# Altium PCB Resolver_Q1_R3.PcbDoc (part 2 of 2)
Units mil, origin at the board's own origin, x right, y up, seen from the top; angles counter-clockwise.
Board outline 2524 x 1600 mil, 2 copper layers (Top Layer, Bottom Layer), stack 62 mil thick; 100 components, 53 nets, 290 pads, 103 vias.
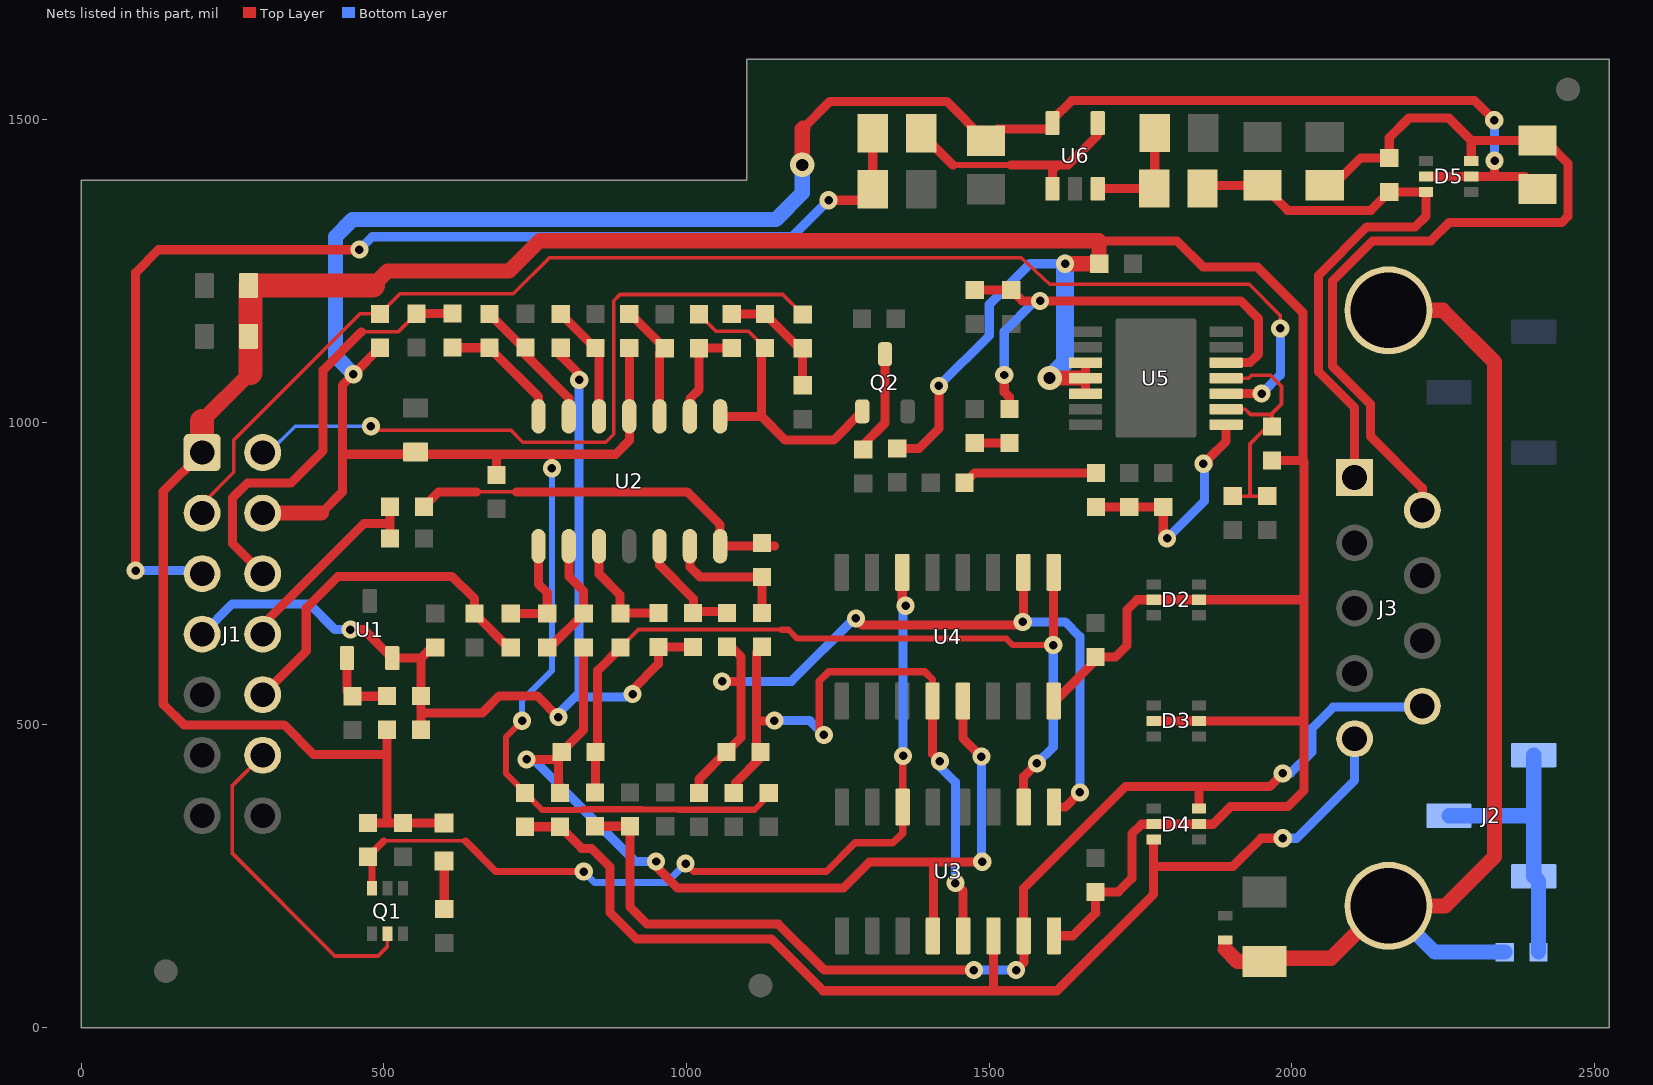
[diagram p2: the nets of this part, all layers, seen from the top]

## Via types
v1: diameter 30, hole 14, Top Layer to Bottom Layer, 80 vias
v2: diameter 23.5, hole 10, Top Layer to Bottom Layer, tented both sides, 12 vias
v3: diameter 40, hole 20, Top Layer to Bottom Layer, 4 vias
v4: diameter 30, hole 14, Top Layer to Bottom Layer, tented both sides, 3 vias
v5: diameter 23.5, hole 10, Top Layer to Bottom Layer, 3 vias
v6: diameter 30, hole 14, Top Layer to Bottom Layer, tented top, 1 vias

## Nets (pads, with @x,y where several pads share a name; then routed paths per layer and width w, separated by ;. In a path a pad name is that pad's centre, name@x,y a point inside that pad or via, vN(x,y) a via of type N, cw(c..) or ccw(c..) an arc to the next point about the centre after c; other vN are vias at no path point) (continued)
ICOS+: R19.1 R21.1 R22.2 U3.1 U4.2 | length 1370.7
  Top Layer w6: v1@1274.95,665 1271.94,668.02 v1(1280,676.08)
  Top Layer w15: R22.2@1020.74,387.81 1020.74,410.15 1066.14,455.54 R19.1@1066.36,455.54 1090.44,479.62 1090.44,571 ; v1(1059,571.97) 1089.47,571.97 1090.44,571 ; R21.1@1071.46,631.44 1090.44,612.47 1090.44,571 ; v1(1280,676.08) v1@1290,666.08 ; v1@1290,665 v4@1555.57,665 ; v4@1551.28,666 v4(1555.57,670.28) 1556.57,671.29 U4.2@1556.57,752.14 ; U3.1@1607.14,364.35 1625.68,364.35 v1(1650,388.67)
  Bottom Layer w15: v1@1063.21,571.97 1173.5,571.97 1277.61,676.08 v1(1280,676.08) ; v4(1555.57,670.28) 1625.64,670.28 1650,645.92 v1(1650,388.67)
ICOS-: R17.1 R18.2 R19.2 U3.13 U4.12 | length 1122.3
  Top Layer w12: v1(1227.2,483.67) 1219.44,491.42 1219.44,572.48 1234.98,588.02 1393.54,588.02 1406.57,574.99 U4.12@1406.57,539.54
  Top Layer w15: R18.2@1078.23,387.81 1078.23,387.86 1081.18,390.81 1081.18,404.44 1122.36,445.63 R19.2@1122.36,455.54 1116.02,461.89 1116.02,506.83 ; R17.1@1125,629.15 1116.02,620.17 1116.02,506.83 ; v1(1145.22,507.21) 1144.84,506.83 1116.02,506.83 ; U4.12@1406.57,539.54 1406.57,452.2 v1(1418.78,440) ; v1(1444.37,238.88) 1457.14,226.11 U3.13@1457.14,151.75
  Bottom Layer w15: v1(1145.22,507.21) 1203.65,507.21 v1(1227.2,483.67) ; v1(1418.78,440) 1418.78,431.22 1444.37,405.63 v1(1444.37,238.88)
INH: J1.12 Q1.2 | length 537.1
  Top Layer w6: J1.12@300,450 250,400 250,287.54 419.26,118.28 490.41,118.28 506.04,133.91 Q1.2@506.04,155.22
INH_CMOS: Q1.6 R26.1 U3.6 U4.6 | length 1457.4
  Top Layer w6: 499.82,308.5 634.54,308.5
  Top Layer w12: Q1.6@480.45,230.02 480.45,275.56 R26.1@473.82,282.19 499.82,308.19 499.82,308.5 ; 634.54,308.5 685.19,257.86 v1(830.31,257.86) ; v1(998.71,271.02) 1011.68,258.05 1231.31,258.05 1278.59,305.32 1341.4,305.32 1357.14,321.07 U3.6@1357.14,364.35 1357.14,448.24 v1(1357.9,449)
  Top Layer w15: U4.6@1356.57,752.14 1356.57,702.43 v4(1362,697)
  Bottom Layer w12: v1(830.31,257.86) 848.27,239.9 967.59,239.9 v1(998.71,271.02)
  Bottom Layer w15: v1(1357.9,449) 1357.9,692.9 v4(1362,697)
ISIN+: R7.1 R10.1 R11.2 U3.2 U4.1 | length 1414.2
  Top Layer w6: R10.1@891.26,627.97 920.94,657.65 1168.25,657.65 1168.62,657.28
  Top Layer w10: 1157,657.28 1168.62,657.28 1183.39,642.51 1212.23,642.51 1212.36,642.65 1528.31,642.65 1538.95,632 v6(1606,632)
  Top Layer w15: R11.2@849.01,388.67 850,389.65 R7.1@850,455.54 853.19,458.73 853.19,589.9 R10.1@891.26,627.97 ; U3.2@1557.14,364.35 1557.14,414.59 v1(1579,436.44) ; v6@1606.57,632 U4.1@1606.57,752.14
  Bottom Layer w15: v1(1579,436.44) 1606,463.45 v6(1606,632)
ISIN-: R5.1 R6.2 R7.2 U3.12 U4.13 | length 1579.8
  Top Layer w15: v1(735.96,443.05) 781.5,443.05 R7.2@788.46,450 ; R6.2@791.26,387.81 788.46,390.61 R7.2@788.46,450 ; R5.1@830.31,627.97 830.31,491.86 R7.2@794,455.54 R7.2@788.46,450 ; v1(950,274.46) 950,266.22 985.84,230.38 1259.35,230.38 1302.31,273.33 1481.98,273.33 v4@1488.75,280.09 ; U3.12@1407.14,151.75 1407.14,169.91 1408,170.76 1408,271.87 ; U4.13@1456.57,539.54 1456.57,478.37 v1(1487.19,447.76)
  Bottom Layer w15: v1(735.96,443.05) 746.89,443.05 915.47,274.46 v1(950,274.46) ; v1(1487.19,447.76) 1487.19,275.49 v4(1488.75,273.94)
NetC9_1: C9.1 R27.2 R28.1 U5.1 | length 394.2
  Top Layer w15: R27.2@1676.45,860.05 R28.1@1731.45,860.05 C9.1@1787.65,860.05 1787.65,814.37 v1(1793.91,808.1) ; v1@1861.93,931.39 1861.93,939.39 1891.46,968.92 U5.1@1891.46,996.12
  Bottom Layer w15: v1(1793.91,808.1) 1856,870.19 1856,925.46 v1@1861.93,931.39
  other v1: 1854,931.46
NetC10_2: C10.2 R27.1 | length 223.5
  Top Layer w15: C10.2@1459.57,900 1475.63,916.05 R27.1@1676.45,916.05
NetC11_1: C11.1 R35.1 U2.2 | length 173.1
  Top Layer w15: U2.2@1005.68,1009.86 1005.68,1038.84 1020.74,1053.91 C11.1@1020.74,1122.36 1074.71,1122.36 R35.1@1075,1122.65
NetC11_2: C11.2 Q2.1 R31.1 U2.1 | length 518.5
  Top Layer w6: C11.2@1020.74,1178.36 1048.45,1150.65 1102,1150.65 R31.1@1130,1122.65
  Top Layer w15: U2.1@1055.68,1009.86 1123.99,1009.86 ; R31.1@1130,1122.65 1123.99,1116.64 1123.99,1009.86 ; Q2.1@1290.6,1018.08 1243.11,970.59 1163.25,970.59 1123.99,1009.86
NetC12_2: C12.2 R33.1 R36.2 U5.2 U5.4 | length 447.3
  Top Layer w6: U5.2@1891.46,1021.71 1923.11,1021.71 1931.91,1012.9 1965.78,1012.9 1982.99,1030.11 1982.99,1059.43 1964.86,1077.56 1933.53,1077.56 1928.86,1072.89 U5.4@1891.46,1072.89 U5.4@1892.17,1072.17 ; C12.2@1902.5,878 1930.93,878 ; R36.2@1959.36,878 1930.93,878 ; 1967.3,1011.38 1967.3,986.28 1953.05,986.28 1930.93,964.16 1930.93,878
NetC13_2: C13.2 R31.2 R34.1 R35.2 | length 201.6
  Top Layer w15: R35.2@1075,1178.65 R31.2@1130,1178.65 1186.41,1122.24 R34.1@1192.03,1122.24 C13.2@1192.03,1061.04
NetC14_2: C14.2 R39.1 | length 57.4
  Top Layer w15: C14.2@1476.23,965.72 R39.1@1533.62,965.72
NetC15_1: C15.1 R39.2 R40.1 U5.5 | length 822
  Top Layer w15: R40.1@1476.23,1218.5 C15.1@1536.47,1218.5 1554.41,1200.57 1588.16,1200.57 1915.37,1200.57 1945,1170.93 1945,1112.68 1930.8,1098.48 U5.5@1891.46,1098.48 ; v1(1525,1078.11) 1525,1050.34 1533.62,1041.72 R39.2@1533.62,1021.72
  Bottom Layer w15: v1(1525,1078.11) 1525,1149.8 1575.77,1200.57 v1@1588.16,1200.57
  other v1: 1584.16,1200.57
NetD1_1: D1.1 R14.2 | length 79.5
  Top Layer w15: D1.1@599.26,275.2 600,274.46 R14.2@600,196
NetJ2_1: J2.1 J2.2 J2.3 R52.1 | length 469.5
  Bottom Layer w25: J2.2@2259.73,350 2397.47,350 2399.69,352.21 ; J2.1@2399.69,450 2399.69,352.21 ; R52.1@2407.71,124.67 2407.71,241.98 J2.3@2399.69,250 2399.69,352.21
NetQ2_3: Q2.3 R32.1 | length 172.4
  Top Layer w15: R32.1@1292.22,955.01 1292.22,963.07 1328,998.85 Q2.3@1328,1112.57
NetR3_1: R3.1 R8.2 U1.1 | length 124
  Top Layer w15: U1.1@439.39,610.41 439.39,556.57 R8.2@448.54,547.42 504.89,547.42 R3.1@505.5,548.04
NetR4_1: R4.1 R5.2 U2.9 | length 205
  Top Layer w15: R4.1@770.04,627.97 774.31,627.97 R5.2@830.31,683.97 830.31,720.83 805.68,745.46 U2.9@805.68,795.29
NetR4_2: R4.2 R9.1 U2.8 | length 177.5
  Top Layer w15: R9.1@709.81,683.97 R4.2@770.04,683.97 770.04,718.19 755.68,732.55 U2.8@755.68,795.29
NetR10_2: R10.2 R12.2 U2.10 | length 188.9
  Top Layer w15: U2.10@855.68,795.29 855.68,749.32 890,715 890,685.23 R10.2@891.26,683.97 892.33,685.04 R12.2@953.62,685.04
NetR16_1: R16.1 R17.2 U2.13 | length 217.3
  Top Layer w15: U2.13@1005.68,795.29 1005.68,761.25 1022.39,744.54 R16.1@1125,744.54 1125,693.16 R17.2@1129.01,689.16
NetR16_2: R16.2 R20.1 U2.14 | length 646.9
  Top Layer w6: 653.17,885.06 719.59,885.06
  Top Layer w15: R20.1@566.3,860.57 590.79,885.06 653.17,885.06 ; 719.59,885.06 1001.13,885.06 1055.68,830.51 U2.14@1055.68,795.29 1145.22,795.29
NetR21_2: R21.2 R23.2 U2.12 | length 192.2
  Top Layer w15: U2.12@955.68,795.29 955.68,764.25 1012,707.93 1012,686.32 1013.13,687.44 R21.2@1071.46,687.44
NetR29_1: R29.1 R37.2 U2.3 | length 197.9
  Top Layer w15: R29.1@905.68,1178.65 907.91,1178.65 R37.2@964.2,1122.36 955.68,1113.84 U2.3@955.68,1009.86
NetR41_1: R41.1 R42.2 U2.6 | length 226
  Top Layer w15: R41.1@674.47,1179.11 730.18,1123.4 R42.2@734.21,1123.4 734.21,1111.45 805.68,1039.99 U2.6@805.68,1009.86
NetR41_2: R41.2 R43.1 U2.7 | length 208
  Top Layer w15: R43.1@613.65,1123.69 614.23,1123.11 R41.2@674.47,1123.11 755.68,1041.9 U2.7@755.68,1009.86
NetR44_2: R44.2 R45.2 U2.5 | length 196.2
  Top Layer w15: R45.2@792.42,1179.11 848.58,1122.94 R44.2@849.84,1122.94 855.68,1117.11 U2.5@855.68,1009.86
NetR49_1: R49.1 U6.1 U6.4 | length 396.4
  Top Layer w10: 1440.26,1425 1536.32,1425
  Top Layer w15: R49.1@1387.8,1477.46 1440.26,1425 ; 1536.32,1425 1613.37,1425 ; U6.1@1604.57,1385.87 1604.57,1416.2 1613.37,1425 ; U6.4@1679.37,1494.13 1679.37,1474.13 1630.24,1425 1613.37,1425
NetR50_2: R50.2 R51.2 U6.3 | length 189.5
  Top Layer w15: U6.3@1679.37,1385.87 1762.05,1385.87 R50.2@1772.64,1396.46 ; R50.2@1772.64,1386.46 R50.2@1772.64,1396.46 ; R51.2@1773.57,1477.92 1773.57,1406.23 1772.64,1405.3 R50.2@1772.64,1396.46
NTC: C22.1 J1.5 R49.2 | length 1971.7
  Top Layer w15: v1(90,755) 90,1247.33 127.67,1285 459.57,1285 v1(459.75,1285.18) ; v1(1234.72,1366.74) 1289.55,1366.74 C22.1@1307.8,1385 R49.2@1307.8,1477.46
  Bottom Layer w15: v1(90,755) 195,755 J1.5@200,750 ; v1(459.75,1285.18) 480.99,1306.41 1174.39,1306.41 v1(1234.72,1366.74)
NTC+: C21.2 C23.1 D5.6 J3.6 R48.1 | length 1501.8
  Top Layer w15: C23.1@2054.45,1391.34 2068.13,1391.34 2113.25,1436.46 C21.2@2161,1436.46 2161,1470.04 2193.64,1502.68 2259.26,1502.68 2296.45,1465.48 ; J3.6@2215.61,854.76 2215.61,891.34 2130,976.95 2130,1030 2067.06,1092.94 2067.06,1233.25 2133.6,1299.79 2229.67,1299.79 2259.7,1329.82 2445.97,1329.82 2456.15,1340 2456.15,1427.72 2418.46,1465.41 R48.1@2405.58,1465.41 2395.58,1455.41 2385.37,1465.62 2296.59,1465.62 2296.45,1465.48 ; D5.6@2296.45,1431.64 2296.45,1465.48
NTC-: C21.1 C24.1 D5.3 J3.1 R50.1 | length 1017.5
  Top Layer w15: R50.1@1852.64,1396.46 1857.76,1391.34 C24.1@1951.81,1391.34 1993.15,1350 2130.55,1350 C21.1@2161,1380.46 D5.3@2221.65,1380.46 2221.65,1340.58 2203.73,1322.66 2124.12,1322.66 2044.18,1242.72 2044.18,1083.47 2103.8,1023.85 J3.1@2103.8,908.69
OCOS: C8.2 J1.8 R20.2 | length 347.7
  Top Layer w15: J1.8@300,650 300,665.63 467.51,833.14 510.25,833.14 ; C8.2@510.25,808.1 510.25,833.14 ; R20.2@510.25,860.57 510.25,833.14
OEXC: C16.2 J1.6 R43.2 | length 713.6
  Top Layer w6: 463.02,1149.26 523.69,1149.26 C16.2@553.84,1179.4
  Top Layer w15: J1.6@300,750 250,800 250,874.94 275.06,900 346.95,900 400,953.05 400,1086.23 463.02,1149.26 ; C16.2@553.84,1179.4 554.13,1179.69 R43.2@613.65,1179.69
OSIN: C3.2 J1.10 R9.2 | length 595.1
  Top Layer w15: J1.10@300,550 372.05,622.04 372.05,692.88 424.63,745.46 612.68,745.46 650,708.14 C3.2@650,683.97 706,627.97 R9.2@709.81,627.97
OT/SHDN: J1.3 R46.1 U5.3 | length 2235.1
  Top Layer w6: J1.3@200,850 200,864.95 252.3,917.25 252.3,970.73 460.68,1179.11 R46.1@493.74,1179.11 526.79,1212.15 713.95,1212.15 773.72,1271.93 1552.95,1271.93 1600,1227.87 1929.54,1227.87 1981,1176.41 v1(1981,1155)
  Top Layer w15: U5.3@1891.46,1047.3 v1(1950,1047.3)
  Bottom Layer w15: v1(1950,1047.3) 1981,1078.3 v1(1981,1155)
PWM: J1.2 R34.2 | length 1164.9
  Top Layer w6: v1(478.82,993.5) 485.63,986.69 710.12,986.69 729.77,967.04 866.79,967.04 879.81,980.05 879.81,1200.57 890.41,1211.17 1159.1,1211.17 R34.2@1192.03,1178.24
  Bottom Layer w6: J1.2@300,950 310.19,950 353.69,993.5 v1(478.82,993.5)
SHIELD_GND: C19.1 J3.10 J3.11 R47.2 R52.2 | length 1798.1
  Top Layer w15: 1890,129.77 R47.2@1890,144.8
  Top Layer w25: 1890,129.77 1910.22,109.54 C19.1@1955,109.54 ; C19.1@1955,114.54 2064.78,114.54 2151.05,200.82 2253.41,200.82 2335,282.41 2335,1099.55 2249.48,1185.07 J3.10@2151.05,1185.07
  Bottom Layer w25: J3.11@2159.7,201.01 2236.05,124.67 R52.2@2351.71,124.67
SIN+: D4.6 J3.9 R11.1 R13.2 U3.15 | length 1846.4
  Top Layer w15: R11.1@849.01,332.67 R13.2@906.57,332.67 906.57,225.79 906.9,205 906.9,199.18 934.95,171.13 1151.92,171.13 1228.05,95 v1(1475,95) ; v1(1544.49,95) 1557.62,108.13 1557.62,139.52 1557.14,140 U3.15@1557.14,151.75 1557.14,230.16 1725.22,398.24 1844.91,398.24 ; D4.6@1846.67,361.61 1846.67,396.48 1844.91,398.24 ; v1(1985,420) 1963.24,398.24 1844.91,398.24
  Bottom Layer w15: v1(1475,95) v1(1544.49,95) ; v1(1985,420) 1997.79,420 2032.94,455.15 2032.94,493.97 2068.33,529.36 J3.9@2206.96,529.36
SIN-: D4.3 J3.5 R2.1 R6.1 U3.14 | length 1898.2
  Top Layer w15: R2.1@733.43,331.81 R6.1@791.26,331.81 826.92,296.15 843.09,296.15 874,265.24 874,190.03 917.4,146.63 1140.24,146.63 1225.87,61 1612.19,61 1771.87,220.68 1771.87,266.5 ; 1507.14,65 U3.14@1507.14,151.75 ; D4.3@1771.87,310.43 1771.87,266.5 ; v1(1985,312.93) 1949.3,312.93 1902.53,266.16 1772.21,266.16 1771.87,266.5
  Bottom Layer w15: v1(1985,312.93) 2008.07,312.93 2103.8,408.65 2103.8,466.18 J3.5@2095.14,474.83
Va: C1.1 C2.1 C5.2 C6.2 C7.2 D1.2 D2.2 D2.5 D3.2 D3.5 D4.2 D4.5 J1.1 R1.2 R25.2 R26.2 R30.2 R33.2 U3.16 U4.16 U5.10 U5.11 U5.12 | length 6331.2
  Top Layer w15: J1.1@195,955 J1.1@200,950 135.83,885.82 135.83,534.17 170,500 335.52,500 384.64,450.88 505.45,450.88 ; R26.2@473.82,338.19 505.45,338.19 ; R1.2@505.5,492.04 505.45,450.88 ; D1.2@599.26,338.19 R25.2@531.63,338.19 505.45,338.19 ; R30.2@1348.22,956.93 1384.42,956.93 1417.11,989.63 v1(1417.11,1060.08) ; U4.16@1606.57,539.54 1608.91,539.54 C7.2@1681.83,612.47 ; U3.16@1607.14,151.75 1638.22,151.75 1676.25,189.77 1675.88,190.13 C6.2@1675.88,224.28 1713.46,224.28 1735.86,246.68 1735.86,320.04 1751.84,336.02 D4.2@1771.87,336.02 D4.5@1846.67,336.02 1869.8,336.02 1898.79,365 1993.35,365 2020,391.65 2020,505 ; U5.11@1658.76,1073.3 U5.11@1659.17,1072.89 ; U5.12@1659.17,1047.3 U5.11@1659.17,1072.89 ; U5.10@1659.17,1098.48 U5.11@1659.17,1072.89 ; C7.2@1675.88,612.47 C7.2@1681.83,612.47 ; 1681.76,1299.79 1810.17,1299.79 1853.48,1256.48 1942.98,1256.48 2018.17,1181.3 2018.17,936.95 ; D3.2@1771.87,506.83 D3.5@1846.67,506.83 2018.17,506.83 2020,505 ; R33.2@1967.3,930.28 1973.98,936.95 2018.17,936.95 ; 505.45,338.19 505.45,450.88 ; C7.2@1681.83,612.47 1709,612.47 1727.86,631.33 1727.86,690.11 1744.58,706.83 D2.2@1772.04,706.83 D2.5@1846.85,706.83 2018.17,706.83 2020,705 ; 2018.17,936.95 2020,935.12 2020,705 ; 2020,505 2020,705
  Top Layer w25: 200,1001.9 280,1081.9 ; 481.81,1225.78 506.04,1250 707.27,1250 757.05,1299.79 1681.76,1299.79 C5.2@1681.81,1261.91 v1(1625.49,1261.91) ; v3(1600,1073.3) U5.11@1658.76,1073.3
  Top Layer w40: J1.1@200,950 200,1001.9 ; 280,1081.9 280,1225.78 481.81,1225.78
  Bottom Layer w15: v1(1417.11,1060.08) 1500.23,1143.2 1500.23,1194.6 1567.55,1261.91 v1@1625.45,1261.91
  Bottom Layer w30: v3(1600,1073.3) 1625.45,1098.75 v1@1625.45,1261.91
Vcc: C4.1 C18.2 C20.1 D5.2 D5.5 J1.4 R2.2 R15.2 R29.2 R46.2 R48.2 U2.4 U6.5 | length 4777.1
  Top Layer w10: v1(728.51,506.83) 702.17,480.49 702.17,419.62 729.05,392.73 728.51,392.73 R2.2@733.43,387.81 761.43,359.81 827.95,359.81 828.93,360.79 926.91,360.79 927.16,360.54 985.26,360.54 985.87,359.93 1112.28,359.93 1112.41,359.81 1136.03,383.43 R15.2@1136.03,387.81 ; 777.39,947.14 777.39,924.39 v1(777.74,924.04)
  Top Layer w15: 396.84,850 431.67,884.82 431.67,947.14 ; R46.2@493.74,1123.11 v1(450,1079.37) 431.67,1061.04 431.67,947.14 ; C18.2@686.19,913.06 686.19,947.14 ; R29.2@905.68,1122.65 U2.4@905.68,1009.86 905.68,969.87 882.95,947.14 777.39,947.14 686.19,947.14 ; 1192.81,1485.69 1237.12,1530 1429.74,1530 C20.1@1494.74,1465 1513.88,1484.13 1604.57,1484.13 U6.5@1604.57,1494.13 1604.57,1499.59 1636.36,1531.38 2302.09,1531.38 v1(2334.48,1499) ; D5.2@2221.65,1406.05 D5.5@2296.45,1406.05 2335,1406.05 ; v1(2335,1432.05) 2335,1406.05 ; R48.2@2386.45,1385.46 2386.45,1404.54 2384.94,1406.05 2335,1406.05 ; 431.67,947.14 552.64,947.14 686.19,947.14
  Top Layer w25: J1.4@300,850 396.84,850 ; v3(1191.41,1425.31) 1191.41,1484.29 1192.81,1485.69
  Bottom Layer w10: v1(728.51,506.83) 728.51,540.67 777.74,589.9 v1(777.74,924.04)
  Bottom Layer w15: v1(2334.48,1499) 2335,1498.48 v1(2335,1432.05)
  Bottom Layer w25: v1(450,1079.37) 420.03,1109.34 420.03,1306.41 448.62,1335 1147.84,1335 1191.41,1378.57 v3(1191.41,1425.31)
VREF1/2: C17.1 J1.7 R1.1 R3.2 R12.1 R23.1 R45.1 U1.2 | length 1708.1
  Top Layer w15: v1(445,657.65) 466.95,657.65 U1.2@514.19,610.41 561.55,610.41 ; R1.1@561.38,491.97 R1.1@561.38,492.04 ; R3.2@561.38,548.04 R3.2@561.38,548.23 ; R1.1@561.5,492.04 561.5,519.97 ; R3.2@561.5,548.04 561.5,519.97 ; R3.2@561.55,548.04 561.55,610.41 ; C17.1@585,627.97 579.12,627.97 561.55,610.41 ; v1(788.46,513.04) 753.53,547.97 691.11,547.97 663.11,519.97 561.5,519.97 ; R45.1@792.42,1123.11 792.42,1109.67 822.88,1079.2 v1(822.88,1070.11) ; v1(911,551) 911,558.51 953.62,601.13 R12.1@953.62,629.04 R23.1@1010.73,629.04
  Bottom Layer w15: J1.7@200,650 200.1,650 250,699.9 377.04,699.9 419.29,657.65 v1(445,657.65) ; v1(788.46,513.04) 788.46,518.77 816.21,546.52 ; v1(822.88,1070.11) 822.88,553.2 816.21,546.52 ; v1(911,551) 903.49,551 899.01,546.52 816.21,546.52
pads on no net: FID1.1 FID2.1 FID3.1 J3.2 J4.1 J4.2 J4.3 U3.4 U4.4 U5.7 U5.8

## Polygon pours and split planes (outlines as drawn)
GND on Bottom Layer "BOTTOM_LAYER_GND_P000" (solid, remove dead copper, pour order 0): 2400,50 2470,120 2470,1485.32 2405.32,1550 1200,1550 1150,1500 1150,1350 100,1350 50,1300 50,100 100,50
Vcc on Top Layer "TOP_LAYER_VCC_P006" (solid, remove dead copper, pour order 6): 50,706.83 50,330.04 99.75,280.28 1105.28,280.28 1194,369 1194,1281.3 624.47,1281.3
Vcc on Top Layer "TOP_LAYER_VCC_P004" (solid, remove dead copper, pour order 4): 1399.89,1375 2350.28,1375 2382.99,1407.71 2382.99,1505.54 2338.53,1550 1200,1550 1150,1500 1150,1375
Va on Top Layer "TOP_LAYER_VA_P002" (solid, remove dead copper, pour order 2): 177.12,913.62 453.5,1190 2009.47,1190 2018.17,1181.3 2018.17,1259.68 1942.85,1335 523.18,1335 453.95,1265.78 291.46,1265.78 177.12,1151.44

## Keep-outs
Keep-Out Layer:
  text ".Layer_Name" at 577,-858.49 h60

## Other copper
Top Layer:
  rectangle net Va: 1600,1053.91 1682.3,1093.66
  text ".Layer_Name" at 577,-858.49 h60
Bottom Layer:
  text ".Layer_Name" at 577,-858.49 h60

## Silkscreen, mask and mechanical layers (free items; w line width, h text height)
Top Overlay:
  text "DAC" at 366.95,920 h40 r90
  text "EXC" at 366.95,720 h40 r90
  text "NTC" at 160.53,715 h40 r90
  text "X-  X+" at 1961.45,629.15 h60 r90
  text "COS" at 366.95,606.9 h40 r90
  text "SIN" at 366.95,516.97 h40 r90
  text "C-  C+" at 1959.36,460.12 h60 r90
  text "INH" at 366.95,419.41 h40 r90
  text "CTL" at 369.65,312.93 h40 r90
  text "S-  S+" at 1961.12,293.12 h60 r90
  text "RESOLVER" at 724.61,124.09 h80
  text "'.PRJ_Number'.PCB_Rev" at 726.2,50 h70
  text ".Layer_Name" at 577,-858.49 h60
Bottom Overlay:
  text ".Layer_Name" at 577,-858.49 h60
Top Paste:
  text ".Layer_Name" at 577,-858.49 h60
Bottom Paste:
  text ".Layer_Name" at 577,-858.49 h60
Top Solder:
  rectangle: 1705,979 1845,1167.36
  text ".Layer_Name" at 577,-858.49 h60
  text ".Layer_Name" at 577,-858.49 h60
Bottom Solder:
  text ".Layer_Name" at 577,-858.49 h60
Drill Guide:
  text ".Layer_Name" at 577,-858.49 h60
M1 Board Outline:
  the board outline again, w10
  text ".Layer_Name" at 577,-858.49 h60
M2 Board Dimensions:
  rectangle: 0,-275 125,-150
  rectangle: 125,-400 500,-275
  lines w7: 0,-275 1000,-275 ; 125,-400 125,-150 ; 250,-400 250,-150 ; 500,-400 500,-150 ; 750,-400 750,-150 ; 0,-400 1000,-400 1000,-150 0,-150 0,-400
  text ".Layer_Name" at 577,-858.49 h60
M3 3D STEP Top:
  text ".Layer_Name" at 577,-858.49 h60
M4 3D STEP Bottom:
  text ".Layer_Name" at 577,-858.49 h60
M5 Assembly Top:
  lines w10: -292,-930.17 6308,-930.17 ; -292,-726.83 6310,-726.83 ; -292,-523.5 -292,-1133.5 3713,-1133.5 6310,-1133.5 6310,-523.5 -291.5,-523.5 -291.5,-1133.5 1284,-1133.5 ; 2173,-1133.5 2173,-523.5 ; 3440,-726.83 3440,-523.5 ; 4280,-726.83 4280,-523.5 ; 4902,-1140 4902,-937.17
  text "COMPONENTS MARKED 'DNP' SHOULD NOT BE POPULATED." at 1153.5,-318.5 h60
  text "ASSEMBLY VARIANT:" at 1153,-434 h60
  text ".VariantName" at 2189,-434 h60
  text "PCB VIEWED FROM TOP SIDE" at -228.5,-655.67 h60
  text "BOARD #:" at 2248,-655.67 h60
  text ".PRJ_Number" at 2793.5,-655.67 h60
  text "REV:" at 3638,-655.67 h60
  text ".PCB_Rev" at 3929.5,-655.67 h60
  text "SVN REV:" at 4476,-655.67 h60
  text ".VersionControl_RevNumber" at 4982,-655.67 h60
  text "TID #:" at 2248,-859 h60
  text ".TID" at 2793.5,-859 h60
  text "PLOT NAME =" at -228.5,-1064.34 h60
  text ".plot_File_Name" at 577,-1064.34 h60
  text "GENERATED    :" at 2250,-1064.34 h60
  text ".Print_Date" at 3119.5,-1064.34 h60
  text ".Print_Time" at 3848.5,-1064.34 h60
  text "TEXAS INSTRUMENTS" at 5113,-1064.34 h60
M6 Assembly Bottom:
  lines w10: -292.5,-727.33 6309.5,-727.33 ; -290.5,-930.67 6309.5,-930.67 ; 1115.5,-1140.5 1115.5,-937.67 ; 1737.5,-727.33 1737.5,-524 ; 2577.5,-727.33 2577.5,-524 ; 3844.5,-1134 3844.5,-524 ; 4733.5,-1134 6309,-1134 6309,-524 -292.5,-524 -292.5,-1134 2304.5,-1134 6309.5,-1134 6309.5,-524
  text "COMPONENTS MARKED 'DNP' SHOULD NOT BE POPULATED." at 6102,-318 h60
  text ".VariantName" at 5058,-434 h60
  text "ASSEMBLY VARIANT:" at 6097,-434 h60
  text ".VersionControl_RevNumber" at 1035.5,-656.17 h60
  text "SVN REV:" at 1541.5,-656.17 h60
  text ".PCB_Rev" at 2088,-656.17 h60
  text "REV:" at 2379.5,-656.17 h60
  text ".PRJ_Number" at 3224,-656.17 h60
  text "BOARD #:" at 3769.5,-656.17 h60
  text "PCB VIEWED FROM BOTTOM SIDE" at 6246,-656.17 h60
  text ".TID" at 3224,-859.5 h60
  text "TID #:" at 3769.5,-859.5 h60
  text "TEXAS INSTRUMENTS" at 904.5,-1064.84 h60
  text ".Print_Time" at 2169,-1064.84 h60
  text ".Print_Date" at 2898,-1064.84 h60
  text "GENERATED    :" at 3767.5,-1064.84 h60
  text ".plot_File_Name" at 5440.5,-1064.84 h60
  text "PLOT NAME =" at 6246,-1064.84 h60
M9 Title Sheet:
  drawing of 57 lines, arcs and shapes, not listed
  text "1" at 739.84,8036.5 h70
  text "2" at 3235.5,8036.5 h70
  text "3" at 5724.84,8036.5 h70
  text "4" at 8231.51,8036.5 h70
  text "5" at 10730.5,8036.5 h70
  text "6" at 13235.5,8036.5 h70
  text "A" at -416.5,6893.5 h70
  text "A" at 14383.5,6893.5 h70
  text "B" at -416.5,4513.5 h70
  text "B" at 14383.5,4513.5 h70
  text "C" at -416.5,2138.5 h70
  text "C" at 14383.5,2138.5 h70
  text "PROJECT TITLE:" at 11343.5,277.5 h45
  text ".PRJ_Title" at 11393.5,144.17 h70
  text "DESIGNED FOR:" at 11343.5,-23.5 h45
  text ".PRJ_Customer" at 11393.5,-163.5 h70
  text "D" at -416.5,-231.5 h70
  text "D" at 14383.5,-231.5 h70
  text "FILE NAME:" at 11343.5,-323.5 h45
  text ".PCB_File_Name_No_Path" at 11393.5,-443.5 h70
  text "Texas Instruments (TI) and/or its licensors do not warrant the accuracy or completeness of this specification" at 6374,-605.34 h45
  text "ENGINEER:" at 11343.5,-613.5 h45
  text "LAYOUT BY:" at 12848.5,-613.5 h45
  text "or any information contained therein. TI and/or its licensors do not warrant that this design will meet" at 6329.01,-718 h45
  text ".PRJ_Engineer" at 11393.5,-768.49 h70
  text ".PCB_Layout" at 12899,-768.49 h70
  text "the specifications, will be suitable for your application or fit for any particular purpose, or will operate in" at 6329.01,-830.67 h45
  text ".Layer_Name" at 577,-858.49 h60
  text "ALTIUM DESIGNER VERSION:" at 12848.5,-923.5 h45
  text "an implementation. TI and/or its licensors do not warrant that the design is production worthy. You should" at 6329.01,-943.33 h45
  text "completely validate and test your design implementation to confirm the system functionality for your application." at 6374,-1056 h45
  text ".print_Scale" at 11393.5,-1056.83 h70
  text ".Application_BuildNumber" at 12899,-1056.83 h70
  text "1" at 739.84,-1263.5 h70
  text "2" at 3235.5,-1263.5 h70
  text "3" at 5724.84,-1263.5 h70
  text "4" at 8231.51,-1263.5 h70
  text "5" at 10730.5,-1263.5 h70
  text "6" at 13235.5,-1263.5 h70
M10 Fab Notes:
  drawing of 189 lines, arcs and shapes, not listed
  text "DESIGN INFORMATION" at 12382.02,6356.17 h60
  text "MIN. TRACK WIDTH:" at 11737.46,6224.05 h60
  text "8" at 12833.7,6224.05 h60
  text "MIL" at 12988.46,6224.05 h60
  text "MIN. CLEARANCE:" at 11737.46,6099.92 h60
  text "0.2" at 12773.7,6099.93 h60
  text "mm" at 12988.46,6099.92 h60
  text "MIN. VIA PAD SIZE:" at 11737.46,5975.8 h60
  text "24" at 12803.71,5975.8 h60
  text "MIL" at 12988.46,5975.8 h60
  text "0.05mm (2MIL)" at 12432.46,5845.9 h60
  text "MINIMUM ANNULAR RING" at 11408.23,5837.67 h60
  text "EXTERNAL" at 13140.46,5837.67 h60
  text "PER" at 11608.23,5727.55 h60
  text "IPC-D-275 CLASS 2 LEVEL C" at 11828.23,5727.54 h60
  text "MIL, HOLES" at 13316.46,5627.07 h60
  text "+/-" at 12924,5618.48 h60
  text "+/-" at 13778,5618.48 h60
  text "REGISTRATION TOLERANCES:" at 11408.23,5617.42 h60
  text "METAL" at 12608,5617.42 h60
  text "5" at 13184.2,5617.42 h60
  text "3" at 14017.2,5617.42 h60
  text "MIL" at 14133.46,5617.42 h60
  text "HOLE SIZE TOLERANCE (UNLESS OTHERWISE SPECIFIED):" at 11408.23,5519.1 h60
  text "+/-" at 13778,5516.23 h60
  text "3" at 14017.2,5515.17 h60
  text "MIL" at 14133.46,5515.17 h60
  text "MATERIAL:" at 11333.46,5377.52 h60
  text "FR-4 High Tg" at 12319.9,5249 h60
  text "X" at 12175.46,5241.01 h60
  text "FR-408" at 11754.46,5236.49 h60
  text "OTHER" at 13242.46,5236.49 h60
  text "62 MIL (1.6mm) +/-10%" at 12074.56,5093.46 h60
  text "X" at 11954.46,5091.01 h60
  text "THICKNESS:" at 11408.23,5085.24 h60
  text "OTHER" at 13359.46,5085.24 h60
  text "TOLERANCE:" at 11408.23,4946.92 h60
  text "X" at 12256.46,4946.92 h60
  text "ANSI IPC-6012 TYPE 3 CLASS 2" at 12434.48,4946.92 h60
  text "OTHER +/-" at 12434.46,4802.73 h60
  text "BOW & TWIST:" at 11408.23,4657.54 h60
  text "X" at 12256.46,4657.54 h60
  text "ANSI IPC-6012 TYPE 3 CLASS 2" at 12434.48,4657.54 h60
  text "OTHER +/-" at 12434.46,4510.85 h60
  text "DRILLING:" at 11333.46,4380.23 h60
  text "NC_DRILL FILES" at 13094.46,4275.04 h60
  text "REFERENCE:" at 11408.23,4271.1 h60
  text "X" at 12065.46,4271.01 h60
  text "AS SHOWN" at 12243.46,4271.1 h60
  text "X" at 12966.46,4271.1 h60
  text "OTHER" at 13392.46,4128.85 h60
  text "PTH COPPER THICKNESS:" at 11407.91,4125.32 h60
  text "X" at 12547.14,4125.32 h60
  text "20-30 um" at 12675.14,4125.32 h60
  text "BOARD FINISH:" at 11333.46,3977.73 h60
  text "SILKSCREEN:" at 11488.68,3867.6 h60
  text "X" at 12446.46,3867.6 h60
  text "TOP" at 12563.46,3867.6 h60
  text "X" at 12956.46,3867.6 h60
  text "BOTTOM" at 13074.46,3867.6 h60
  text "SILKSCREEN COLOR:" at 11488.68,3712.41 h60
  text "X" at 12445.46,3712.41 h60
  text "WHITE" at 12563.46,3712.41 h60
  text "OTHER" at 13074.46,3712.41 h60
  text "X" at 12576.46,3568.96 h60
  text "GREEN" at 12694.46,3568.96 h60
  text "OTHER" at 13312.46,3568.96 h60
  text "SOLDER RESIST COLOR:" at 11488.68,3562.1 h60
  text "X" at 12576.46,3414.71 h60
  text "MATTE" at 12694.46,3414.71 h60
  text "SEMI-GLOSS" at 13312,3414.07 h60
  text "IMMERSION GOLD (ENIG)" at 12394.46,3241.94 h60
  text "ENEPIG" at 13732,3234.72 h60
  text "SURFACE FINISH:" at 11333.46,3233.72 h60
  text "X" at 11500,3096.4 h60
  text "IMM. TIN/SILVER OR EQUIV" at 11663,3096.4 h60
  text "OTHER" at 13094.46,3092.47 h60
  text "ARRAY/PANEL:" at 11333.46,2937.09 h60
  text "CUT AND TRIM PER M1 BOARD OUTLINE" at 12394.46,2928.87 h60
  text "N.C. ROUTE" at 12394.46,2792.9 h60
  text "X" at 13082.46,2792.9 h60
  text "V. SCORE" at 13260.46,2792.9 h60
  text "CERTIFICATION:" at 11333.46,2663.77 h60
  text "MATERIALS AND WORKMANSHIP FOR ALL PCBS" at 12058.46,2663.77 h60
  text "TO MEET OR EXCEED THE REQUIREMENTS OF:" at 12058.46,2569.71 h60
  text "X" at 11695.97,2441.08 h60
  text "ANSI IPC-A-600F CLASS ->" at 11823.96,2441.08 h60
  text "X" at 13471.97,2441.08 h60
  text "2" at 13581.96,2441.08 h60
  text "1" at 13266.96,2439.58 h60
  text "3" at 13935.96,2439.58 h60
  text "X" at 12507.97,2293.39 h60
  text "RoHS" at 12635.96,2293.39 h60
  text "OTHER" at 13280.36,2293.39 h60
  text "PER ORDER" at 13677.42,2293.39 h60
  text "ALL BOARDS MUST MEET OR EXCEED UL94-V0 REQUIREMENTS." at 11361,2139.57 h60
  text "PCB MUST BEAR THE UL94V-0 UL REGISTERED MATERIAL ID NUMBER" at 11361,2023.5 h60
  text "ADDITIONAL REQUIREMENTS:" at 11333.46,1854.08 h60
  text "MICROSECTION:" at 11408.23,1746.95 h60
  text "YES" at 12313.96,1746.95 h60
  text "REQUIRED" at 13175.46,1602.62 h60
  text "BARE BOARD ELEC. TEST:" at 11408.23,1599.76 h60
  text "X" at 12600.5,1599.76 h60
  text "NONE" at 12713.96,1599.76 h60
  text "PER ORDER" at 13767.46,1599.76 h60
  text "XX MIL VIAS REQUIRE NON-CONDUCTIVE FILL AND PLANARIZE" at 11576.38,1394.82 h59
  text "XX MIL VIAS REQUIRE CONDUCTIVE FILL AND PLANARIZE" at 11584.38,1290.84 h60
  text "OUTER XX MIL TRACES REQUIRE 50 OHM SINGLE-ENDED IMPEDANCE" at 11583.39,1127.46 h58
  text "LAYER 2 & 3 (INNER LAYERS) XX MIL WIDE, XX MIL SPACE / TRACES REQUIRE 100 OHM DIFFERENTIAL IMPEDANCE" at 11575.39,891.74 h60
  text ".Layer_Name" at 577,-858.49 h60
M11 Gerber Information:
  lines w10: -292,-930.17 6308,-930.17 ; -292,-726.83 6310,-726.83 ; -292,-523.5 -292,-1133.5 3713,-1133.5 6310,-1133.5 6310,-523.5 -291.5,-523.5 -291.5,-1133.5 1284,-1133.5 ; 2173,-1133.5 2173,-523.5 ; 3440,-726.83 3440,-523.5 ; 4280,-726.83 4280,-523.5 ; 4902,-1140 4902,-937.17
  text "ALL ARTWORK VIEWED FROM TOP SIDE" at -228.5,-655.67 h60
  text "BOARD #:" at 2248,-655.67 h60
  text ".PRJ_Number" at 2793.5,-655.67 h60
  text "REV:" at 3638,-655.67 h60
  text ".PCB_Rev" at 3929.5,-655.67 h60
  text "SVN REV:" at 4476,-655.67 h60
  text ".VersionControl_RevNumber" at 4982,-655.67 h60
  text "LAYER NAME =" at -228.5,-858.49 h60
  text "TID #:" at 2248,-859 h60
  text ".TID" at 2793.5,-859 h60
  text "PLOT NAME =" at -228.5,-1064.34 h60
  text ".plot_File_Name" at 577,-1064.34 h60
  text "GENERATED    :" at 2250,-1064.34 h60
  text ".Print_Date" at 3119.5,-1064.34 h60
  text ".Print_Time" at 3848.5,-1064.34 h60
  text "TEXAS INSTRUMENTS" at 5113,-1064.34 h60
M12 Stackup:
  drawing of 191 lines, arcs and shapes, not listed
  text "Layer" at 9811.59,7334.94 h60
  text "Name" at 10221.51,7334.94 h60
  text "Material" at 11151.25,7334.94 h60
  text "Thickness" at 12011.02,7334.94 h60
  text "Constant" at 12660.85,7334.94 h60
  text "Board Layer Stack" at 13230.71,7334.94 h60
  text "1" at 9811.59,7214.94 h60
  text "Top Overlay" at 10221.51,7214.94 h60
  text "2" at 9811.59,7094.94 h60
  text "Top Solder" at 10221.51,7094.94 h60
  text "Solder Resist" at 11151.25,7094.94 h60
  text "0.40mil" at 12011.02,7094.94 h60
  text "3.5" at 12660.85,7094.94 h60
  text "3" at 9811.59,6974.94 h60
  text "Top Layer" at 10221.51,6974.94 h60
  text "Copper" at 11151.25,6974.94 h60
  text "1.40mil" at 12011.02,6974.94 h60
  text "4" at 9811.59,6854.94 h60
  text "Dielectric1" at 10221.51,6854.94 h60
  text "FR-4" at 11151.25,6854.94 h60
  text "59.20mil" at 12011.02,6854.94 h60
  text "4.8" at 12660.85,6854.94 h60
  text "5" at 9811.59,6734.94 h60
  text "Bottom Layer" at 10221.51,6734.94 h60
  text "Copper" at 11151.25,6734.94 h60
  text "1.40mil" at 12011.02,6734.94 h60
  text "6" at 9811.59,6614.94 h60
  text "Bottom Solder" at 10221.51,6614.94 h60
  text "Solder Resist" at 11151.25,6614.94 h60
  text "0.40mil" at 12011.02,6614.94 h60
  text "3.5" at 12660.85,6614.94 h60
  text "7" at 9811.59,6494.94 h60
  text "Bottom Overlay" at 10221.51,6494.94 h60
  text ".Layer_Name" at 577,-858.49 h60
M13 Component Bodies Top:
  text ".Layer_Name" at 577,-858.49 h60
M14 Component Bodies Bottom:
  text ".Layer_Name" at 577,-858.49 h60
M15 Courtyards Top:
  text ".Layer_Name" at 577,-858.49 h60
M16 Courtyards Bottom:
  text ".Layer_Name" at 577,-858.49 h60
Drill Drawing:
  circle w10: c3134,1159 r27.63
  lines w10: 3106.37,509.78 3134,523.59 3161.62,509.78 3147.81,537.4 3161.62,565.03 3134,551.22 3106.37,565.03 3120.18,537.4 3106.37,509.78 ; 3106.37,661.72 3134,634.1 3161.62,661.72 3134,689.35 3106.37,661.72 ; 3106.37,758.42 3161.62,758.42 3161.62,813.67 3106.37,813.67 3106.37,758.42 ; 3106.37,896.55 3120.18,896.55 3134,882.74 3147.81,896.55 3161.62,896.55 3147.81,910.36 3161.62,924.18 3147.81,924.18 3134,937.99 3120.18,924.18 3106.37,924.18 3120.18,910.36 3106.37,896.55 ; 3106.37,1062.31 3161.62,1062.31 3134,1007.06 3106.37,1062.31
  lines w12: 3056.28,472.48 6287.77,472.48 ; 3056.28,1218.4 6287.77,1218.4 ; 3394.14,348.16 3394.14,1342.72 ; 3726.14,348.16 3726.14,1342.72 ; 4362.7,348.16 4362.7,1342.72 ; 4621.84,348.16 4621.84,1342.72 ; 4997,348.16 4997,1342.72 ; 5721.33,348.16 5721.33,1342.72 ; 3056.28,348.16 6287.77,348.16 6287.77,1342.72 3056.28,1342.72 3056.28,348.16
  text "Symbol" at 3130.87,1255.7 h72
  text "Quantity" at 3431.44,1255.7 h72
  text "Finished Hole Size" at 3763.44,1255.7 h72
  text "Plated" at 4400,1255.7 h72
  text "Hole Type" at 4659.14,1255.7 h72
  text "Drill Layer Pair" at 5034.3,1255.7 h72
  text "Hole Tolerance" at 5758.63,1255.7 h72
  text "15" at 3431.44,1131.38 h60
  text "10.00mil (0.254mm)" at 3763.44,1131.38 h60
  text "PTH" at 4400,1131.38 h60
  text "Round" at 4659.14,1131.38 h60
  text "Top Layer - Bottom Layer" at 5034.3,1131.38 h60
  text "84" at 3431.44,1007.06 h60
  text "14.00mil (0.356mm)" at 3763.44,1007.06 h60
  text "PTH" at 4400,1007.06 h60
  text "Round" at 4659.14,1007.06 h60
  text "Top Layer - Bottom Layer" at 5034.3,1007.06 h60
  text "4" at 3431.44,882.74 h60
  text "20.00mil (0.508mm)" at 3763.44,882.74 h60
  text "PTH" at 4400,882.74 h60
  text "Round" at 4659.14,882.74 h60
  text "Top Layer - Bottom Layer" at 5034.3,882.74 h60
  text "14" at 3431.44,758.42 h60
  text "40.16mil (1.020mm)" at 3763.44,758.42 h60
  text "PTH" at 4400,758.42 h60
  text "Round" at 4659.14,758.42 h60
  text "Top Layer - Bottom Layer" at 5034.3,758.42 h60
  text "9" at 3431.44,634.1 h60
  text "40.95mil (1.040mm)" at 3763.44,634.1 h60
  text "PTH" at 4400,634.1 h60
  text "Round" at 4659.14,634.1 h60
  text "Top Layer - Bottom Layer" at 5034.3,634.1 h60
  text "2" at 3431.44,509.78 h60
  text "124.80mil (3.170mm)" at 3763.44,509.78 h60
  text "PTH" at 4400,509.78 h60
  text "Round" at 4659.14,509.78 h60
  text "Top Layer - Bottom Layer" at 5034.3,509.78 h60
  text "128 Total" at 3431.44,385.46 h60
  text ".Layer_Name" at 577,-858.49 h60
M17 Embedded Cavity:
  text ".Layer_Name" at 577,-858.49 h60
M18 Embedded Assembly:
  text ".Layer_Name" at 577,-858.49 h60
M19 Embedded Keepout:
  text ".Layer_Name" at 577,-858.49 h60

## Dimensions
0,-400 to 1000,-400 on M2 Board Dimensions
1100,1600 to 0,0 on M2 Board Dimensions
2524,1600 to 0,1400 on M2 Board Dimensions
